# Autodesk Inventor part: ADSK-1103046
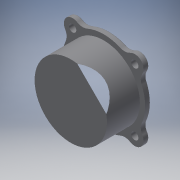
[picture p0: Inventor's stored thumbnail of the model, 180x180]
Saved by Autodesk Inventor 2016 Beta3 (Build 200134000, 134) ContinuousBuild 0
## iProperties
Shininess: 50.0
Length Units: 11272
Angle Units: 11279
Time Units: 11290
Mass Units: 11286
Length Display Precision: 4
Angle Display Precision: 2
Compacted: True
Created: 2000-07
Part Number: ADSK-1103046
Document SubType Name: Modeling
Description: ENGINE COVER - REAR
Mass: 4.64243 g
Surface Area: 23.1415 cm^2
Volume: 1.71307 cm^3
Density: 2.71 g/cm^3
Material: Aluminum-6061
Appearance: Grey
Density: 0.0
Volumn: 0.0
Area: 0.0
PropertySet Name: Model Information
Control State: 0
Master: False
Checked Out: False
Author: Autodesk, Inc.
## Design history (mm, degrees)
node "Extrusion1" dims "d8" = 1.5875, "d9" = 0
  sketch "Sketch3"
    geometry: C1 r 2.54 at (-10.091, 9); C2 r 2.54 at (7.909, 9); C3 r 2.54 at (7.909, -9); C4 r 2.54 at (-10.091, -9); A1 r 1.048 centre (-10.091, 9) between (-10.08, 7.952) and (-9.043, 8.989); A2 r 1.048 centre (7.909, 9) between (7.898, 7.952) and (6.861, 8.989); A3 r 1.048 centre (-10.091, -9) between (-10.08, -7.952) and (-9.043, -8.989); A4 r 1.048 centre (7.909, -9) between (6.861, -8.989) and (7.898, -7.952); A5 r 12.002 centre (-1.091, 0) between (6.861, 8.989) and (-9.043, 8.989); A6 r 12.002 centre (-1.091, 0) between (7.898, -7.952) and (7.898, 7.952); A7 r 12.002 centre (-1.091, 0) between (-10.08, 7.952) and (-10.08, -7.952); A8 r 12.002 centre (-1.091, 0) between (-9.043, -8.989) and (6.861, -8.989)
    constraints: 16 point on circle, 12 centre point, 9 equal radius, 4 coincident, 2 horizontal alignment, 2 vertical alignment, 1 other
    dimensions: "d0" = 18 distance of A4.centre A3.centre; "d1" = 18 distance of A1.centre A3.centre; "d2" = 2.0955 diameter of A2; "d3" = 5.08 diameter of C2; "d4" = 9 horizontal distance of A1.centre A5.centre (= 0.5 x d1); "d5" = 9 horizontal distance of A3.centre A5.centre (= 0.5 x d0); "d7" = 12.0015 radius of A6
node "Fillet1" dims "d10" = 3.175
node "Extrusion2" dims "d12" = 9.525, "d13" = 0
  sketch "Sketch4"
    geometry: C1 r 10.477 at (-1.091, 0); A1 r 12.002 centre (-1.091, 0) between (-12.09, 4.802) and (-12.09, -4.802) reference
    constraints: 1 centre point, 1 coincident
    dimensions: "d11" = 20.955 diameter of C1
node "Extrusion3" dims "d15" = 9.525, "d16" = 0
  sketch "Sketch5"
    geometry: C1 r 8.89 at (1.091, 0); C2 r 10.477 at (1.091, 0) reference; A1 r 12.001 centre (1.091, 0) between (-9.908, 4.802) and (-9.908, -4.802) reference
    constraints: 1 centre point, 1 coincident
    dimensions: "d14" = 1.5875 radial gap between concentric circles of C2 C1
node "Fillet2" dims "d17" = 0.381
body "Solid1"
other parameters: "d6" = 24.003
